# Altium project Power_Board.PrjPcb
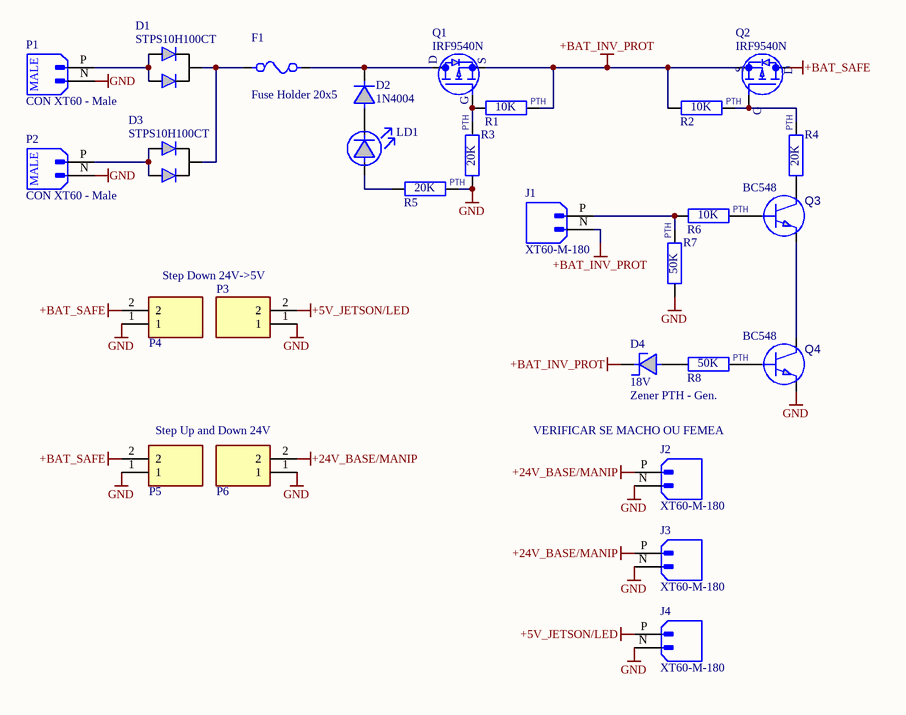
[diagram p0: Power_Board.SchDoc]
1 sheet, 28 parts. Net scope: global (net labels, ports and power ports of the same name join across sheets).
Board file: Power_Board_PCB.PcbDoc

## Sheet Power_Board.SchDoc: Omnicare Power Board
size A4; Author: Thiago M.; DrawnBy: Thiago M.; SheetNumber: 1; SheetTotal: 1

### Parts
D1  STPS10H100CT  [TO-220AB]
D2  1N4004  [DO41]
D3  STPS10H100CT  [TO-220AB]
D4  Zener PTH - Gen.  value 18V  [DO41 - Zener]
F1  Fuse Holder 20x5  [FUSE HOLDER 20x5]
J1  XT60-M-180  [AMASS_XT60-M]
J2  XT60-M-180  [AMASS_XT60-M]
J3  XT60-M-180  [AMASS_XT60-M]
J4  XT60-M-180  [AMASS_XT60-M]
LD1  LED PTH - Gen.  [DO41]  (value not drawn)
P1  CON XT60 - Male  [CON XT60 MALE]
P2  CON XT60 - Male  [CON XT60 MALE]
P3  CON KF2 EDGRC-5.08-02P  [BORNE 5.08 RA 2P]  (value not drawn)
P4  CON KF2 EDGRC-5.08-02P  [BORNE 5.08 RA 2P]  (value not drawn)
P5  CON KF2 EDGRC-5.08-02P  [BORNE 5.08 RA 2P]  (value not drawn)
P6  CON KF2 EDGRC-5.08-02P  [BORNE 5.08 RA 2P]  (value not drawn)
Q1  IRF9540N  [TO-220AB]
Q2  IRF9540N  [TO-220AB]
Q3  BC548  [TO-92 LPM]  (value not drawn)
Q4  BC548  [TO-92 LPM]  (value not drawn)
R1  10K  [RES PTH]
R2  10K  [RES PTH]
R3  20K  [RES PTH]
R4  20K  [RES PTH]
R5  20K  [RES PTH]
R6  10K  [RES PTH]
R7  50K  [RES PTH]
R8  50K  [RES PTH]

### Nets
+5V_JETSON/LED: J4.P(POS) P3.2
+24V_BASE/MANIP: J2.P(POS) J3.P(POS) P6.2
+BAT_INV_PROT: D4.1(K) J1.N(NEG) Q1.3(S) Q2.3(S) R1.1 R2.2
+BAT_SAFE: P4.2 P5.2 Q2.2(D)
GND: J2.N(NEG) J3.N(NEG) J4.N(NEG) P1.N(NEG) P2.N(NEG) P3.1 P4.1 P5.1 P6.1 Q4.3(E) R3.2 R5.1 R7.2
NetD1_1: D1.1(A1) D1.3(A2) P1.P(POS)
NetD1_2: D1.2(K) D3.2(K) F1.1
NetD2_1: D2.1(K) F1.2 Q1.2(D)
NetD2_2: D2.2(A) LD1.1(K)
NetD3_1: D3.1(A1) D3.3(A2) P2.P(POS)
NetD4_2: D4.2(A) R8.2
NetJ1_P: J1.P(POS) R6.2 R7.1
NetLD1_2: LD1.2(A) R5.2
NetQ1_1: Q1.1(G) R1.2 R3.1
NetQ2_1: Q2.1(G) R2.1 R4.1
NetQ3_1: Q3.1(C) R4.2
NetQ3_2: Q3.2(B) R6.1
NetQ3_3: Q3.3(E) Q4.1(C)
NetQ4_2: Q4.2(B) R8.1

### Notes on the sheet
- Step Down 24V->5V
- Step Up and Down 24V
- (near J2) VERIFICAR SE MACHO OU FEMEA

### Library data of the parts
D1 D3 = STPS10H100CT: Diodo Schottky de 2x5A e 100V de corrente reversa
D2 = 1N4004: DIODE - PTH 400V 1A; Vf: 1.1V
D4 = Zener PTH - Gen.: DIODE - PTH Zener generic
J1-J4 = CMP-004-000000-5: Plug; DC supply; XT60; male; PIN: 2; for cable; soldered; 30A; 500V; MP: XT60-M; MF: AMASS
LD1 = LED PTH - Gen.: Generic PTH Led
P3-P6 = CON KF2 EDGRC-5.08-02P: CONECTOR - Borne 2 Vias Macho Passo 5.08mm 90º KF2 EDGRC-5.08-02P Fechado.
Q1 Q2 = IRF9540N: Mosfet PMOS PTH - 23A Id; Id: -22A; Vgs Max: 20V; Vth: -10V
Q3 Q4 = BC548: TRANSISTOR -  TBJ NPN
R1-R8 = RES PTH - Gen.: Generic PTH resistor for general purpose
